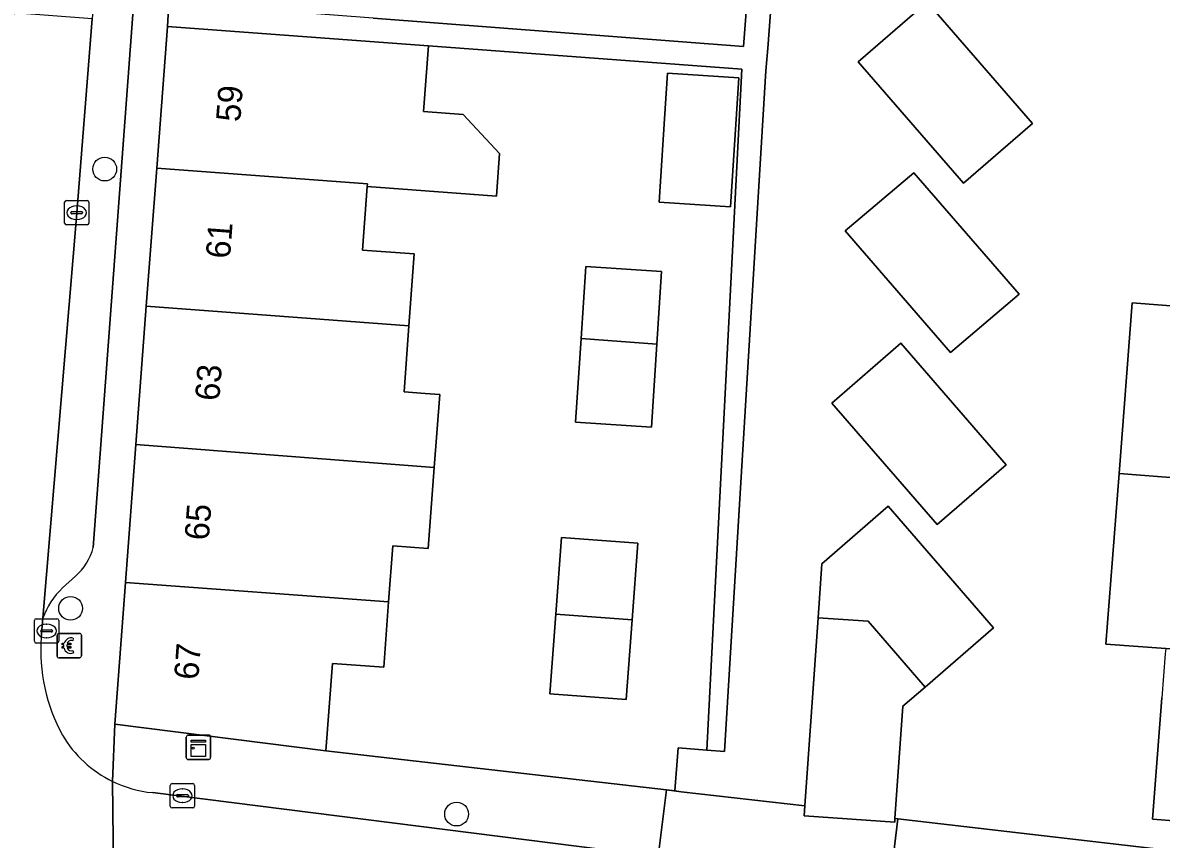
# Model space of a CAD drawing. Extents: x 161838 to 162344, y 381620 to 382160.
# Drawn here: x 161937.3 to 161984.06, y 381784.69 to 381818.23 of the extents above; entities that cross this region are included whole.
import ezdxf

# ---------------------------------------------------------------- set-up
doc = ezdxf.new("R2010")
doc.units = 0
for name, color, linetype in [('IMGEO_Betaalautomaat', 7, 'Continuous'), ('IMGEO_Boom', 7, 'Continuous'), ('IMGEO_Erf', 7, 'Continuous'), ('IMGEO_Kast', 7, 'Continuous'), ('IMGEO_Kolk', 7, 'Continuous'), ('IMGEO_Muur', 7, 'Continuous'), ('IMGEO_Pand', 7, 'Continuous'), ('IMGEO_Pand_nummerreeks', 7, 'Continuous'), ('IMGEO_Parkeervlak_open', 7, 'Continuous'), ('IMGEO_Rijbaan_lokaal_open', 7, 'Continuous'), ('IMGEO_Voetpad_open', 7, 'Continuous')]:
    doc.layers.add(name, color=color, linetype=linetype)

msp = doc.modelspace()

# ---------------------------------------------------------------- linework, layer by layer
at = {"layer": 'IMGEO_Betaalautomaat'}
for p, q in [((161938.707, 381792.214), (161938.707, 381793.055)), ((161938.707, 381793.055), (161938.707, 381792.214)), ((161938.782, 381793.138), (161939.623, 381793.138)), ((161939.623, 381793.138), (161938.782, 381793.138)), ((161939.369, 381792.943), (161939.352, 381792.843)), ((161939.706, 381793.064), (161939.706, 381792.223)), ((161939.706, 381792.223), (161939.706, 381793.064)), ((161938.99, 381792.602), (161938.99, 381792.67)), ((161939.111, 381792.67), (161939.111, 381792.602)), ((161939.356, 381792.437), (161939.378, 381792.35)), ((161939.632, 381792.139), (161938.791, 381792.139)), ((161938.791, 381792.139), (161939.632, 381792.139))]:
    msp.add_line(p, q, dxfattribs=at)
for points in [[(161938.99, 381792.67), (161938.921, 381792.67), (161938.921, 381792.739), (161939, 381792.739)], [(161938.995, 381792.533), (161938.921, 381792.533), (161938.921, 381792.602), (161938.99, 381792.602)], [(161939.122, 381792.739), (161939.269, 381792.739), (161939.269, 381792.67), (161939.111, 381792.67)], [(161939.111, 381792.602), (161939.269, 381792.602), (161939.269, 381792.533), (161939.125, 381792.533)]]:
    msp.add_lwpolyline(points, dxfattribs=at)
for centre, radius, start, end in [((161938.785, 381793.061), 0.0779, 92.4484, 184.2845), ((161938.785, 381793.061), 0.0779, 92.4484, 184.2845), ((161939.283, 381792.663), 0.293, 73.014, 165.0139), ((161939.629, 381793.061), 0.0779, 2.4484, 94.2845), ((161939.629, 381793.061), 0.0779, 2.4484, 94.2845), ((161939.256, 381792.588), 0.267, 191.8096, 297.0389), ((161939.289, 381792.676), 0.179, 69.3236, 159.5683), ((161939.289, 381792.603), 0.179, 202.7625, 291.8693), ((161938.785, 381792.217), 0.0779, 182.4484, 274.2845), ((161938.785, 381792.217), 0.0779, 182.4484, 274.2845), ((161939.629, 381792.217), 0.0779, 272.4484, 4.2845), ((161939.629, 381792.217), 0.0779, 272.4484, 4.2845)]:
    msp.add_arc(centre, radius, start, end, dxfattribs=at)
at = {"layer": 'IMGEO_Boom'}
for centre in [(161940.664, 381812.223), (161939.263, 381794.173), (161955.119, 381785.72)]:
    msp.add_circle(centre, 0.489, dxfattribs=at)
at = {"layer": 'IMGEO_Erf'}
for points in [[(161970.994, 381859.267), (161970.22, 381848.039), (161970.088, 381846.125), (161969, 381831.764), (161967.896, 381817.185), (161967.827, 381816.258), (161966.128, 381788.286), (161965.392, 381788.344), (161964.225, 381788.435), (161964.087, 381786.67), (161964.343, 381786.64), (161969.419, 381786.055), (161969.969, 381793.786), (161970.127, 381796.004), (161972.849, 381798.365), (161977.175, 381793.376), (161974.364, 381790.938), (161973.452, 381790.147), (161973.124, 381785.533), (161973.243, 381785.519), (161983.732, 381784.311), (161992.738, 381783.267)], [(161951.685, 381818.418), (161966.909, 381817.26), (161967.341, 381822.957)], [(161984.244, 381792.516), (161981.789, 381792.705), (161982.328, 381799.716), (161982.867, 381806.728), (161985.326, 381806.539)], [(161992.143, 381784.853), (161983.703, 381785.505), (161984.088, 381790.491)]]:
    msp.add_lwpolyline(points, dxfattribs=at)
for points in [[(161978.771, 381814.096), (161975.939, 381811.641), (161971.614, 381816.629), (161974.446, 381819.085)], [(161966.829, 381816.332), (161953.962, 381817.283), (161953.763, 381814.591), (161955.384, 381814.471), (161956.886, 381812.857), (161956.757, 381811.113), (161955.662, 381811.194), (161951.45, 381811.505), (161951.257, 381808.891), (161953.379, 381808.734), (161953.161, 381805.783), (161952.961, 381803.071), (161953.829, 381803.007), (161954.424, 381802.963), (161954.202, 381799.962), (161953.956, 381796.631), (161952.497, 381796.739), (161952.328, 381794.439), (161952.13, 381791.752), (161950.015, 381791.908), (161949.749, 381788.319), (161963.737, 381786.71), (161964.087, 381786.67), (161964.225, 381788.435), (161965.392, 381788.344)], [(161963.661, 381814.293), (161963.783, 381816.169), (161966.717, 381815.978), (161966.373, 381810.676), (161963.439, 381810.866)], [(161978.229, 381807.086), (161975.402, 381804.689), (161971.077, 381809.679), (161973.906, 381812.074)], [(161960.23, 381805.259), (161960.422, 381808.222), (161963.541, 381808.02), (161963.347, 381805.028), (161963.126, 381801.614), (161960.007, 381801.816)], [(161977.688, 381800.074), (161974.854, 381797.618), (161970.529, 381802.608), (161973.363, 381805.064)], [(161962.56, 381796.85), (161962.328, 381793.697), (161962.087, 381790.428), (161958.953, 381790.659), (161959.194, 381793.929), (161959.426, 381797.081)]]:
    msp.add_lwpolyline(points, close=True, dxfattribs=at)
at = {"layer": 'IMGEO_Kast'}
for p, q in [((161944.016, 381788.039), (161944.016, 381788.88)), ((161944.016, 381788.88), (161944.016, 381788.039)), ((161944.091, 381788.964), (161944.932, 381788.964)), ((161944.932, 381788.964), (161944.091, 381788.964)), ((161945.016, 381788.889), (161945.016, 381788.048)), ((161945.016, 381788.048), (161945.016, 381788.889)), ((161944.941, 381787.964), (161944.1, 381787.964)), ((161944.1, 381787.964), (161944.941, 381787.964))]:
    msp.add_line(p, q, dxfattribs=at)
for points in [[(161944.211, 381788.754), (161944.811, 381788.754), (161944.811, 381788.669), (161944.211, 381788.669), (161944.211, 381788.754)], [(161944.211, 381788.579), (161944.811, 381788.579), (161944.811, 381788.09), (161944.211, 381788.09), (161944.211, 381788.579)]]:
    msp.add_lwpolyline(points, dxfattribs=at)
msp.add_circle((161944.295, 381788.428), 0.0377, dxfattribs=at)
for centre, start, end in [((161944.094, 381788.886), 92.4484, 184.2845), ((161944.094, 381788.886), 92.4484, 184.2845), ((161944.938, 381788.886), 2.4484, 94.2845), ((161944.938, 381788.886), 2.4484, 94.2845), ((161944.094, 381788.042), 182.4484, 274.2845), ((161944.094, 381788.042), 182.4484, 274.2845), ((161944.938, 381788.042), 272.4484, 4.2845), ((161944.938, 381788.042), 272.4484, 4.2845)]:
    msp.add_arc(centre, 0.0779, start, end, dxfattribs=at)
at = {"layer": 'IMGEO_Kolk'}
for p, q in [((161939.015, 381810.004), (161939.015, 381810.856)), ((161939.09, 381810.93), (161939.942, 381810.93)), ((161939.503, 381810.71), (161939.528, 381810.71)), ((161940.016, 381810.856), (161940.016, 381810.004)), ((161939.274, 381810.424), (161939.274, 381810.436)), ((161939.712, 381810.387), (161939.314, 381810.387)), ((161939.317, 381810.473), (161939.715, 381810.473)), ((161939.758, 381810.436), (161939.758, 381810.424)), ((161939.942, 381809.93), (161939.09, 381809.93)), ((161939.526, 381810.15), (161939.501, 381810.15)), ((161937.776, 381792.819), (161937.776, 381793.671)), ((161937.851, 381793.745), (161938.703, 381793.745)), ((161938.264, 381793.525), (161938.289, 381793.525)), ((161938.777, 381793.671), (161938.777, 381792.819)), ((161938.035, 381793.239), (161938.035, 381793.251)), ((161938.473, 381793.202), (161938.075, 381793.202)), ((161938.078, 381793.288), (161938.476, 381793.288)), ((161938.287, 381792.965), (161938.262, 381792.965)), ((161938.519, 381793.251), (161938.519, 381793.239)), ((161938.703, 381792.745), (161937.851, 381792.745)), ((161943.358, 381786.048), (161943.358, 381786.9)), ((161943.433, 381786.974), (161944.285, 381786.974)), ((161944.359, 381786.9), (161944.359, 381786.048)), ((161943.617, 381786.468), (161943.617, 381786.48)), ((161944.055, 381786.431), (161943.657, 381786.431)), ((161943.66, 381786.517), (161944.058, 381786.517)), ((161943.846, 381786.754), (161943.871, 381786.754)), ((161944.101, 381786.48), (161944.101, 381786.468)), ((161944.285, 381785.974), (161943.433, 381785.974)), ((161943.869, 381786.194), (161943.844, 381786.194))]:
    msp.add_line(p, q, dxfattribs=at)
for points in [[(161939.015, 381810.004), (161939.015, 381810.856)], [(161939.09, 381810.93), (161939.942, 381810.93)], [(161940.016, 381810.856), (161940.016, 381810.004)], [(161939.942, 381809.93), (161939.09, 381809.93)], [(161937.776, 381792.819), (161937.776, 381793.671)], [(161937.851, 381793.745), (161938.703, 381793.745)], [(161938.777, 381793.671), (161938.777, 381792.819)], [(161938.703, 381792.745), (161937.851, 381792.745)], [(161943.358, 381786.048), (161943.358, 381786.9)], [(161943.433, 381786.974), (161944.285, 381786.974)], [(161944.359, 381786.9), (161944.359, 381786.048)], [(161944.285, 381785.974), (161943.433, 381785.974)]]:
    msp.add_lwpolyline(points, dxfattribs=at)
for centre, radius, start, end in [((161939.092, 381810.854), 0.0765, 91.552, 178.448), ((161939.092, 381810.854), 0.0765, 91.552, 178.448), ((161939.94, 381810.854), 0.0765, 1.552, 88.448), ((161939.94, 381810.854), 0.0765, 1.552, 88.448), ((161939.314, 381810.433), 0.0403, 85.8775, 175.7526), ((161939.311, 381810.423), 0.0366, 178.938, 274.7102), ((161939.715, 381810.43), 0.043, 264.8664, 352.4533), ((161939.719, 381810.435), 0.0386, 1.7309, 96.639), ((161939.092, 381810.006), 0.0765, 181.552, 268.448), ((161939.092, 381810.006), 0.0765, 181.552, 268.448), ((161939.94, 381810.006), 0.0765, 271.552, 358.448), ((161939.94, 381810.006), 0.0765, 271.552, 358.448), ((161937.853, 381793.669), 0.0765, 91.552, 178.448), ((161937.853, 381793.669), 0.0765, 91.552, 178.448), ((161938.701, 381793.669), 0.0765, 1.552, 88.448), ((161938.701, 381793.669), 0.0765, 1.552, 88.448), ((161938.075, 381793.248), 0.0403, 85.8775, 175.7526), ((161938.072, 381793.238), 0.0366, 178.938, 274.7102), ((161938.476, 381793.245), 0.043, 264.8664, 352.4533), ((161938.48, 381793.25), 0.0386, 1.7309, 96.639), ((161937.853, 381792.821), 0.0765, 181.552, 268.448), ((161937.853, 381792.821), 0.0765, 181.552, 268.448), ((161938.701, 381792.821), 0.0765, 271.552, 358.448), ((161938.701, 381792.821), 0.0765, 271.552, 358.448), ((161943.435, 381786.898), 0.0765, 91.552, 178.448), ((161943.435, 381786.898), 0.0765, 91.552, 178.448), ((161944.283, 381786.898), 0.0765, 1.552, 88.448), ((161944.283, 381786.898), 0.0765, 1.552, 88.448), ((161943.657, 381786.477), 0.0403, 85.8775, 175.7526), ((161943.654, 381786.467), 0.0366, 178.938, 274.7102), ((161944.058, 381786.474), 0.043, 264.8664, 352.4533), ((161944.062, 381786.479), 0.0386, 1.7309, 96.639), ((161943.435, 381786.05), 0.0765, 181.552, 268.448), ((161943.435, 381786.05), 0.0765, 181.552, 268.448), ((161944.283, 381786.05), 0.0765, 271.552, 358.448), ((161944.283, 381786.05), 0.0765, 271.552, 358.448)]:
    msp.add_arc(centre, radius, start, end, dxfattribs=at)
for centre, major_axis, ratio, start_param, end_param in [((161939.502, 381810.43), (-0.387, 0.002), 0.722429, 4.712389, 7.853982), ((161939.527, 381810.43), (-0.39, 0.002), 0.717154, 1.570796, 4.712389), ((161938.263, 381793.245), (-0.387, 0.002), 0.722429, 4.712389, 7.853982), ((161938.288, 381793.245), (-0.39, 0.002), 0.717154, 1.570796, 4.712389), ((161943.845, 381786.474), (-0.387, 0.002), 0.722429, 4.712389, 7.853982), ((161943.87, 381786.474), (-0.39, 0.002), 0.717154, 1.570796, 4.712389)]:
    msp.add_ellipse(centre, major_axis=major_axis, ratio=ratio, start_param=start_param, end_param=end_param, dxfattribs=at)
at = {"layer": 'IMGEO_Muur'}
for points in [[(161949.749, 381788.319), (161963.737, 381786.71)], [(161963.737, 381786.71), (161964.343, 381786.64)], [(161973.243, 381785.519), (161973.124, 381785.533)], [(161983.732, 381784.311), (161973.243, 381785.519)]]:
    msp.add_lwpolyline(points, dxfattribs=at)
at = {"layer": 'IMGEO_Pand'}
for points in [[(161974.446, 381819.085), (161971.614, 381816.629), (161975.939, 381811.641), (161978.771, 381814.096)], [(161942.8, 381812.254), (161951.458, 381811.612), (161951.45, 381811.505), (161955.662, 381811.194), (161956.757, 381811.113), (161956.886, 381812.857), (161955.384, 381814.471), (161953.763, 381814.591), (161953.962, 381817.283), (161948.225, 381817.707), (161943.238, 381818.075)], [(161963.661, 381814.293), (161963.439, 381810.866), (161966.373, 381810.676), (161966.717, 381815.978), (161963.783, 381816.169)], [(161953.161, 381805.783), (161953.379, 381808.734), (161951.257, 381808.891), (161951.45, 381811.505), (161951.458, 381811.612), (161942.8, 381812.254), (161942.374, 381806.583)], [(161975.402, 381804.689), (161978.229, 381807.086), (161973.906, 381812.074), (161971.077, 381809.679)], [(161960.23, 381805.259), (161963.347, 381805.028), (161963.541, 381808.02), (161960.422, 381808.222)], [(161953.161, 381805.783), (161942.374, 381806.583), (161941.947, 381800.912), (161954.202, 381799.962), (161954.424, 381802.963), (161953.829, 381803.007), (161952.961, 381803.071)], [(161993.766, 381805.889), (161985.792, 381806.503), (161985.326, 381806.539), (161982.867, 381806.728), (161982.328, 381799.716), (161984.785, 381799.527), (161993.225, 381798.877)], [(161960.23, 381805.259), (161960.007, 381801.816), (161963.126, 381801.614), (161963.347, 381805.028)], [(161974.854, 381797.618), (161977.688, 381800.074), (161973.363, 381805.064), (161970.529, 381802.608)], [(161941.947, 381800.912), (161941.521, 381795.241), (161952.328, 381794.439), (161952.497, 381796.739), (161953.956, 381796.631), (161954.202, 381799.962)], [(161984.785, 381799.527), (161982.328, 381799.716), (161981.789, 381792.705), (161984.244, 381792.516), (161992.684, 381791.867), (161993.225, 381798.877)], [(161974.364, 381790.938), (161977.175, 381793.376), (161972.849, 381798.365), (161970.127, 381796.004), (161969.969, 381793.786), (161972.022, 381793.64)], [(161962.328, 381793.697), (161962.56, 381796.85), (161959.426, 381797.081), (161959.194, 381793.929)], [(161941.521, 381795.241), (161941.083, 381789.42), (161949.749, 381788.319), (161950.015, 381791.908), (161952.13, 381791.752), (161952.328, 381794.439)], [(161962.328, 381793.697), (161959.194, 381793.929), (161958.953, 381790.659), (161962.087, 381790.428)], [(161974.364, 381790.938), (161972.022, 381793.64), (161969.969, 381793.786), (161969.419, 381786.055), (161969.39, 381785.645), (161973.113, 381785.381), (161973.124, 381785.533), (161973.452, 381790.147)], [(161984.244, 381792.516), (161984.228, 381792.307), (161984.088, 381790.491), (161983.703, 381785.505), (161992.143, 381784.853), (161992.684, 381791.867)]]:
    msp.add_lwpolyline(points, close=True, dxfattribs=at)
at = {"layer": 'IMGEO_Parkeervlak_open'}
for points in [[(161943.525, 381863.595), (161942.846, 381853.998), (161941.932, 381842.594), (161941.187, 381831.869), (161940.353, 381821.056), (161940.242, 381819.615), (161940.145, 381818.394), (161939.516, 381810.43), (161939.514, 381810.412), (161938.12, 381793.764)], [(161940.195, 381796.673), (161942.802, 381831.842)], [(161938.934, 381795.01), (161939.461, 381795.496)]]:
    msp.add_lwpolyline(points, dxfattribs=at)
for centre, radius, start, end in [((161937.927, 381797.27), 2.345, 310.8494, 345.2537), ((161941.163, 381792.665), 3.235, 133.5442, 160.1434)]:
    msp.add_arc(centre, radius, start, end, dxfattribs=at)
at = {"layer": 'IMGEO_Rijbaan_lokaal_open'}
for points in [[(161938.055, 381792.981), (161938.12, 381793.764), (161939.514, 381810.412), (161939.516, 381810.43), (161940.145, 381818.394), (161936.924, 381818.645), (161936.567, 381814.112), (161935.814, 381803.997), (161934.702, 381793.974), (161934.263, 381790.508), (161934.246, 381790.374), (161932.457, 381777.573), (161932.346, 381776.852), (161932.238, 381776.158), (161931.14, 381770.501)], [(161941.065, 381779.861), (161940.987, 381787.064)], [(161940.987, 381787.064), (161941.065, 381779.861), (161974.338, 381775.707), (162008.503, 381771.36), (162010.639, 381770.93)], [(162010.959, 381777.779), (162009.14, 381778.097), (162008.56, 381778.199), (161991.196, 381780.587), (161988.923, 381780.862), (161972.91, 381782.799), (161963.403, 381783.98), (161942.624, 381786.599)]]:
    msp.add_lwpolyline(points, dxfattribs=at)
for centre, radius, start, end in [((161945.26, 381792.443), 7.225, 175.7333, 208.7892), ((161943.108, 381791.429), 4.853, 210.5218, 244.0779), ((161943.108, 381791.417), 4.842, 244.0222, 264.2628)]:
    msp.add_arc(centre, radius, start, end, dxfattribs=at)
at = {"layer": 'IMGEO_Voetpad_open'}
for points in [[(161952.548, 381903.011), (161947.051, 381876.525), (161946.016, 381869.662), (161945.36, 381864.998), (161945.318, 381864.481), (161944.324, 381852.208), (161942.802, 381831.842), (161940.195, 381796.673)], [(161940.987, 381787.064), (161941.083, 381789.42), (161941.521, 381795.241), (161941.947, 381800.912), (161942.374, 381806.583), (161942.8, 381812.254), (161943.238, 381818.075), (161943.294, 381819.057), (161943.706, 381824.556), (161944.105, 381829.905), (161944.504, 381835.255), (161944.903, 381840.603), (161945.302, 381845.953), (161945.701, 381851.302), (161946.1, 381856.651), (161946.51, 381862.151), (161946.659, 381864.312), (161947.853, 381869.993), (161949.023, 381875.557), (161950.193, 381881.121)], [(161939.461, 381795.496), (161938.934, 381795.01)], [(161938.12, 381793.764), (161938.055, 381792.981)], [(161949.749, 381788.319), (161941.083, 381789.42), (161940.987, 381787.064)], [(161942.624, 381786.599), (161963.403, 381783.98), (161963.737, 381786.71), (161949.749, 381788.319)], [(161992.738, 381783.267), (161983.732, 381784.311), (161973.243, 381785.519), (161972.91, 381782.799), (161988.923, 381780.862), (161991.196, 381780.587)]]:
    msp.add_lwpolyline(points, dxfattribs=at)
for points in [[(161951.685, 381818.418), (161948.28, 381818.677), (161943.294, 381819.057), (161943.238, 381818.075), (161948.225, 381817.707), (161953.962, 381817.283), (161966.829, 381816.332), (161965.392, 381788.344), (161966.128, 381788.286), (161967.827, 381816.258), (161967.896, 381817.185), (161969, 381831.764), (161970.088, 381846.125), (161970.22, 381848.039), (161969.057, 381848.126), (161968.975, 381847.151), (161968.71, 381844.168), (161968.315, 381836.822), (161968.079, 381833.459), (161967.869, 381830.476), (161967.703, 381828.106), (161967.341, 381822.957), (161966.909, 381817.26)], [(161969.39, 381785.645), (161969.419, 381786.055), (161964.343, 381786.64), (161964.087, 381786.67), (161963.737, 381786.71), (161963.403, 381783.98), (161972.91, 381782.799), (161973.243, 381785.519), (161973.124, 381785.533), (161973.113, 381785.381)]]:
    msp.add_lwpolyline(points, close=True, dxfattribs=at)
for centre, radius, start, end in [((161937.927, 381797.27), 2.345, 310.8494, 345.2537), ((161941.163, 381792.665), 3.235, 133.5442, 160.1434), ((161945.26, 381792.443), 7.225, 175.7333, 208.7892), ((161943.108, 381791.429), 4.853, 210.5218, 244.0779), ((161943.108, 381791.417), 4.842, 244.0222, 264.2628)]:
    msp.add_arc(centre, radius, start, end, dxfattribs=at)

# ---------------------------------------------------------------- texts
at = {"layer": 'IMGEO_Pand_nummerreeks'}
for s, p in [('59', (161946.231, 381814.139)), ('61', (161945.809, 381808.521)), ('63', (161945.369, 381802.677)), ('65', (161944.938, 381796.946)), ('67', (161944.507, 381791.215))]:
    msp.add_text(s, height=1, rotation=85.6992, dxfattribs=at).set_placement(p)

doc.saveas('drawing.dxf')
